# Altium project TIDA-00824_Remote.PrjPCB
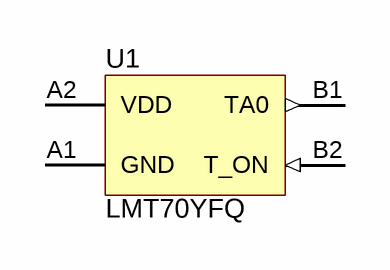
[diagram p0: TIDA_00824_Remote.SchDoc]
TechSupport: http://www.ti.com/support; SCH_Rev: A; PRJ_Title: Temperature Sensing for Wearable Applications; PRJ_Engineer: Emmy Denton; PRJ_Customer: Public Release; PCB_Rev: A; PCB_Layout: Emmy Denton; CopyrightYear: 2015
1 sheet, 1 parts. Net scope: global (net labels, ports and power ports of the same name join across sheets).
Board file: TIDA_00824_Remote.PcbDoc

## Sheet TIDA_00824_Remote.SchDoc
size 431 x 279 mm; Date: Not shown in title block; ApprovedBy: Not shown in title block; CheckedBy: Not shown in title block; Author: Not shown in title block; CompanyName: Not shown in title block; Engineer: Not shown in title block; Organization: Not shown in title block; Address1: Not shown in title block; Address2: Not shown in title block; Address3: Not shown in title block; Address4: Not shown in title block; DocumentNumber: 1; Revision: Use project parameter SCH_Rev; SheetNumber: 1; SheetTotal: 1; PageSetup: Record=PageOptions|CenterHorizontal=True|CenterVertical=True|PrintScale=1.00|XCorrection=1.00|YCorrection=1.00|PrintKind=0|BorderSize=5000000|LeftOffset=0|BottomOffset=0|Orientation=2|PaperLength=1000|PaperWidth=1000|Scale=100|PaperSource=15|PrintQuality=600|MediaType=1|DitherType=10|PaperKind=Letter|PrintScaleMode=1

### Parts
U1  LMT70YFQ  [YFQ0004ACAC]

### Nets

Not connected (* = marked no-connect by the designer): U1 A1(GND) A2(VDD) B1(TA0) B2(T_ON)

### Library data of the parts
U1 = LMT70YFQ: Precise Temperature Sensor with Output Enable TEMPERATURE SENSOR, YFQ0004ACAC; Manufacturer: Texas Instruments; SymbolCreator: a0411947; CompType: IC; U/M: EA

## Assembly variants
001: not fitted FID1 FID2 FID3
